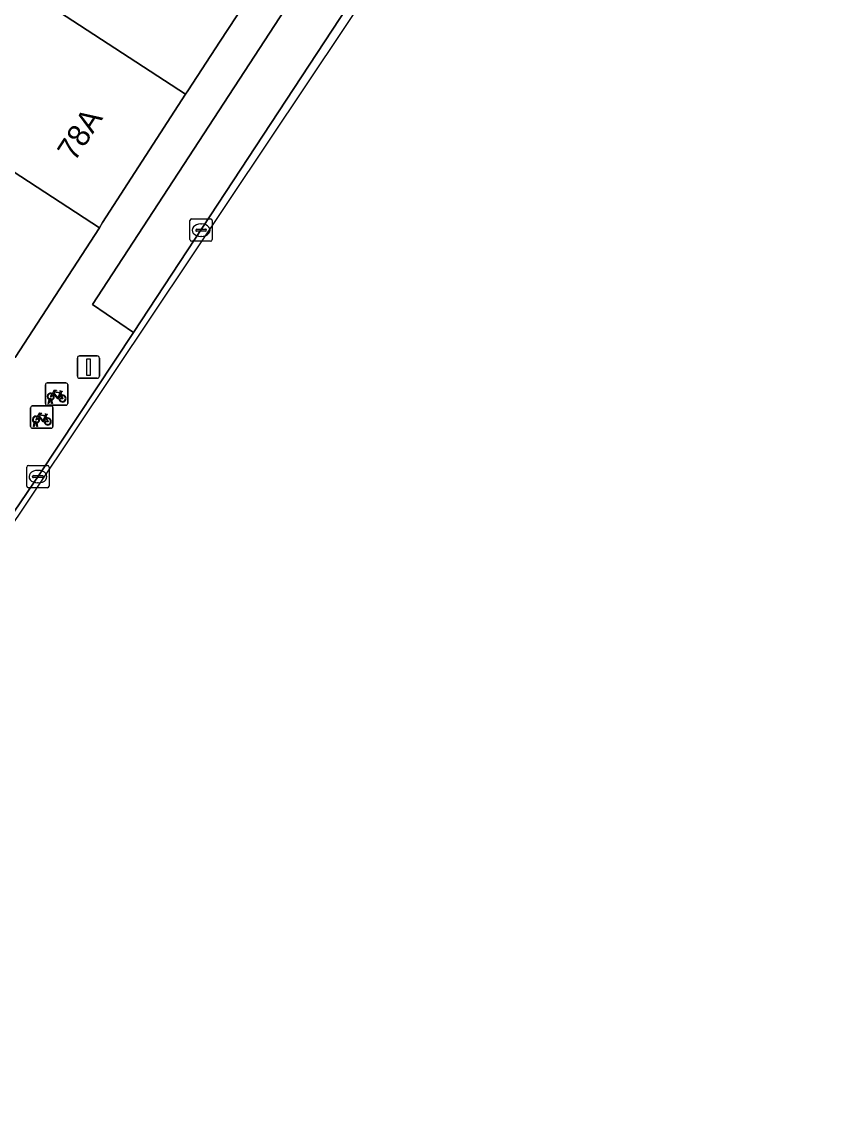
# Model space of a CAD drawing. Extents: x 160102 to 160934, y 382045 to 382923.
# Drawn here: x 160814.44 to 160850.23, y 382615.4 to 382664.84 of the extents above; entities that cross this region are included whole.
import ezdxf

# ---------------------------------------------------------------- set-up
doc = ezdxf.new("R2010")
doc.units = 0
for name, color, linetype in [('IMGEO_Fietsenrek', 7, 'Continuous'), ('IMGEO_Kolk', 7, 'Continuous'), ('IMGEO_Lichtmast', 7, 'Continuous'), ('IMGEO_Pand', 7, 'Continuous'), ('IMGEO_Pand_nummerreeks', 7, 'Continuous'), ('IMGEO_Parkeervlak_open', 7, 'Continuous'), ('IMGEO_Rijbaan_lokaal_gesloten', 7, 'Continuous'), ('IMGEO_Voetpad_open', 7, 'Continuous')]:
    doc.layers.add(name, color=color, linetype=linetype)

msp = doc.modelspace()

# ---------------------------------------------------------------- linework, layer by layer
at = {"layer": 'IMGEO_Fietsenrek'}
for p, q in [((160815.489, 382647.735), (160815.489, 382648.576)), ((160815.489, 382648.576), (160815.489, 382647.735)), ((160815.564, 382648.66), (160816.405, 382648.66)), ((160816.405, 382648.66), (160815.564, 382648.66)), ((160816.489, 382648.585), (160816.489, 382647.744)), ((160816.489, 382647.744), (160816.489, 382648.585)), ((160816.176, 382648.209), (160816.212, 382648.114)), ((160814.901, 382647.629), (160815.742, 382647.629)), ((160815.742, 382647.629), (160814.901, 382647.629)), ((160816.414, 382647.66), (160815.573, 382647.66)), ((160815.573, 382647.66), (160816.414, 382647.66)), ((160815.616, 382647.744), (160815.655, 382647.904)), ((160815.65, 382647.744), (160815.616, 382647.744)), ((160815.685, 382647.892), (160815.65, 382647.744)), ((160815.727, 382647.916), (160815.726, 382647.92)), ((160815.768, 382647.744), (160815.734, 382647.886)), ((160815.758, 382647.927), (160815.759, 382647.92)), ((160815.766, 382647.89), (160815.801, 382647.744)), ((160815.801, 382647.744), (160815.768, 382647.744)), ((160814.826, 382646.704), (160814.826, 382647.545)), ((160814.826, 382647.545), (160814.826, 382646.704)), ((160815.513, 382647.178), (160815.549, 382647.083)), ((160815.826, 382647.554), (160815.826, 382646.713)), ((160815.826, 382646.713), (160815.826, 382647.554)), ((160815.751, 382646.629), (160814.91, 382646.629)), ((160814.91, 382646.629), (160815.751, 382646.629)), ((160814.953, 382646.713), (160814.992, 382646.873)), ((160814.987, 382646.713), (160814.953, 382646.713)), ((160815.022, 382646.861), (160814.987, 382646.713)), ((160815.064, 382646.885), (160815.063, 382646.889)), ((160815.105, 382646.713), (160815.071, 382646.855)), ((160815.095, 382646.896), (160815.096, 382646.889)), ((160815.103, 382646.859), (160815.138, 382646.713)), ((160815.138, 382646.713), (160815.105, 382646.713))]:
    msp.add_line(p, q, dxfattribs=at)
for points in [[(160815.823, 382648.134), (160815.771, 382648.044), (160815.731, 382648.019), (160815.732, 382648.066), (160815.787, 382648.16)], [(160815.802, 382648.186), (160815.897, 382648.35), (160815.983, 382648.336), (160815.985, 382648.327), (160815.929, 382648.316), (160815.902, 382648.271), (160816.158, 382648.23)], [(160816.098, 382647.942), (160816.048, 382647.942), (160815.857, 382648.193), (160815.838, 382648.161)], [(160816.145, 382648.205), (160815.888, 382648.246), (160815.871, 382648.217), (160816.038, 382647.997), (160816.145, 382648.205)], [(160816.193, 382648.107), (160816.163, 382648.184), (160816.054, 382647.966), (160816.097, 382647.966)], [(160816.127, 382647.966), (160816.247, 382647.965), (160816.203, 382648.079)], [(160816.223, 382648.086), (160816.278, 382647.941), (160816.128, 382647.941)], [(160816.158, 382648.23), (160816.183, 382648.279), (160816.177, 382648.283), (160816.154, 382648.287), (160816.142, 382648.294), (160816.141, 382648.297), (160816.143, 382648.302), (160816.238, 382648.287), (160816.24, 382648.277), (160816.23, 382648.264), (160816.218, 382648.258), (160816.204, 382648.264), (160816.176, 382648.209)], [(160815.16, 382647.103), (160815.108, 382647.013), (160815.068, 382646.988), (160815.069, 382647.035), (160815.124, 382647.129)], [(160815.139, 382647.155), (160815.234, 382647.319), (160815.32, 382647.305), (160815.322, 382647.296), (160815.266, 382647.285), (160815.239, 382647.24), (160815.495, 382647.199)], [(160815.435, 382646.911), (160815.385, 382646.911), (160815.194, 382647.162), (160815.175, 382647.13)], [(160815.482, 382647.174), (160815.225, 382647.215), (160815.208, 382647.186), (160815.375, 382646.966), (160815.482, 382647.174)], [(160815.53, 382647.076), (160815.5, 382647.153), (160815.391, 382646.935), (160815.434, 382646.935)], [(160815.495, 382647.199), (160815.52, 382647.248), (160815.514, 382647.252), (160815.491, 382647.256), (160815.479, 382647.263), (160815.478, 382647.266), (160815.48, 382647.271), (160815.575, 382647.256), (160815.577, 382647.246), (160815.567, 382647.233), (160815.555, 382647.227), (160815.541, 382647.233), (160815.513, 382647.178)], [(160815.464, 382646.935), (160815.584, 382646.934), (160815.54, 382647.048)], [(160815.56, 382647.055), (160815.615, 382646.91), (160815.465, 382646.91)]]:
    msp.add_lwpolyline(points, dxfattribs=at)
for centre, radius, start, end in [((160815.567, 382648.582), 0.0779, 92.4484, 184.2845), ((160815.567, 382648.582), 0.0779, 92.4484, 184.2845), ((160816.411, 382648.582), 0.0779, 2.4484, 94.2845), ((160816.411, 382648.582), 0.0779, 2.4484, 94.2845), ((160815.729, 382648.045), 0.159, 62.6766, 242.1369), ((160815.729, 382648.045), 0.129, 63.3192, 238.903), ((160815.729, 382648.045), 0.129, 283.6043, 43.4302), ((160815.729, 382648.045), 0.159, 283.5766, 46.6042), ((160816.256, 382647.961), 0.159, 113.3408, 178.3217), ((160816.256, 382647.961), 0.159, 187.0065, 105.7708), ((160816.256, 382647.961), 0.129, 113.923, 177.9556), ((160816.256, 382647.961), 0.129, 188.6715, 104.5883), ((160814.904, 382647.551), 0.0779, 92.4484, 184.2845), ((160814.904, 382647.551), 0.0779, 92.4484, 184.2845), ((160815.567, 382647.738), 0.0779, 182.4484, 274.2845), ((160815.567, 382647.738), 0.0779, 182.4484, 274.2845), ((160815.709, 382647.916), 0.0499, 12.8025, 158.6934), ((160815.729, 382648.045), 0.159, 253.9967, 271.7867), ((160815.709, 382647.916), 0.0174, 12.8025, 163.4502), ((160815.729, 382648.045), 0.129, 253.415, 269.0204), ((160815.748, 382647.551), 0.0779, 2.4484, 94.2845), ((160815.748, 382647.551), 0.0779, 2.4484, 94.2845), ((160816.411, 382647.738), 0.0779, 272.4484, 4.2845), ((160816.411, 382647.738), 0.0779, 272.4484, 4.2845), ((160815.066, 382647.014), 0.159, 62.6766, 242.1369), ((160815.066, 382647.014), 0.129, 63.3192, 238.903), ((160815.066, 382647.014), 0.129, 283.6043, 43.4302), ((160815.066, 382647.014), 0.159, 283.5766, 46.6042), ((160815.593, 382646.93), 0.159, 113.3408, 178.3217), ((160815.593, 382646.93), 0.159, 187.0065, 105.7708), ((160814.904, 382646.707), 0.0779, 182.4484, 274.2845), ((160814.904, 382646.707), 0.0779, 182.4484, 274.2845), ((160815.046, 382646.885), 0.0499, 12.8025, 158.6934), ((160815.066, 382647.014), 0.159, 253.9967, 271.7867), ((160815.046, 382646.885), 0.0174, 12.8025, 163.4502), ((160815.066, 382647.014), 0.129, 253.415, 269.0204), ((160815.593, 382646.93), 0.129, 113.923, 177.9556), ((160815.593, 382646.93), 0.129, 188.6715, 104.5883), ((160815.748, 382646.707), 0.0779, 272.4484, 4.2845), ((160815.748, 382646.707), 0.0779, 272.4484, 4.2845)]:
    msp.add_arc(centre, radius, start, end, dxfattribs=at)
at = {"layer": 'IMGEO_Kolk'}
for p, q in [((160822.047, 382656.009), (160822.899, 382656.009)), ((160821.972, 382655.083), (160821.972, 382655.935)), ((160822.231, 382655.503), (160822.231, 382655.515)), ((160822.274, 382655.552), (160822.672, 382655.552)), ((160822.46, 382655.789), (160822.485, 382655.789)), ((160822.715, 382655.515), (160822.715, 382655.503)), ((160822.973, 382655.935), (160822.973, 382655.083)), ((160822.899, 382655.009), (160822.047, 382655.009)), ((160822.669, 382655.466), (160822.271, 382655.466)), ((160822.483, 382655.229), (160822.458, 382655.229)), ((160814.655, 382644.034), (160814.655, 382644.886)), ((160814.73, 382644.96), (160815.582, 382644.96)), ((160815.143, 382644.74), (160815.168, 382644.74)), ((160815.656, 382644.886), (160815.656, 382644.034)), ((160814.914, 382644.454), (160814.914, 382644.466)), ((160815.352, 382644.417), (160814.954, 382644.417)), ((160814.957, 382644.503), (160815.355, 382644.503)), ((160815.166, 382644.18), (160815.141, 382644.18)), ((160815.398, 382644.466), (160815.398, 382644.454)), ((160815.582, 382643.96), (160814.73, 382643.96))]:
    msp.add_line(p, q, dxfattribs=at)
for points in [[(160822.047, 382656.009), (160822.899, 382656.009)], [(160821.972, 382655.083), (160821.972, 382655.935)], [(160822.973, 382655.935), (160822.973, 382655.083)], [(160822.899, 382655.009), (160822.047, 382655.009)], [(160814.655, 382644.034), (160814.655, 382644.886)], [(160814.73, 382644.96), (160815.582, 382644.96)], [(160815.656, 382644.886), (160815.656, 382644.034)], [(160815.582, 382643.96), (160814.73, 382643.96)]]:
    msp.add_lwpolyline(points, dxfattribs=at)
for centre, radius, start, end in [((160822.049, 382655.933), 0.0765, 91.552, 178.448), ((160822.049, 382655.933), 0.0765, 91.552, 178.448), ((160822.897, 382655.933), 0.0765, 1.552, 88.448), ((160822.897, 382655.933), 0.0765, 1.552, 88.448), ((160822.271, 382655.512), 0.0403, 85.8775, 175.7526), ((160822.268, 382655.502), 0.0366, 178.938, 274.7102), ((160822.672, 382655.509), 0.043, 264.8664, 352.4533), ((160822.676, 382655.514), 0.0386, 1.7309, 96.639), ((160822.049, 382655.085), 0.0765, 181.552, 268.448), ((160822.049, 382655.085), 0.0765, 181.552, 268.448), ((160822.897, 382655.085), 0.0765, 271.552, 358.448), ((160822.897, 382655.085), 0.0765, 271.552, 358.448), ((160814.732, 382644.884), 0.0765, 91.552, 178.448), ((160814.732, 382644.884), 0.0765, 91.552, 178.448), ((160815.58, 382644.884), 0.0765, 1.552, 88.448), ((160815.58, 382644.884), 0.0765, 1.552, 88.448), ((160814.954, 382644.463), 0.0403, 85.8775, 175.7526), ((160814.951, 382644.453), 0.0366, 178.938, 274.7102), ((160815.355, 382644.46), 0.043, 264.8664, 352.4533), ((160815.359, 382644.465), 0.0386, 1.7309, 96.639), ((160814.732, 382644.036), 0.0765, 181.552, 268.448), ((160814.732, 382644.036), 0.0765, 181.552, 268.448), ((160815.58, 382644.036), 0.0765, 271.552, 358.448), ((160815.58, 382644.036), 0.0765, 271.552, 358.448)]:
    msp.add_arc(centre, radius, start, end, dxfattribs=at)
for centre, major_axis, ratio, start_param, end_param in [((160822.459, 382655.509), (-0.387, 0.002), 0.722429, 4.712389, 7.853982), ((160822.484, 382655.509), (-0.39, 0.002), 0.717154, 1.570796, 4.712389), ((160815.142, 382644.46), (-0.387, 0.002), 0.722429, 4.712389, 7.853982), ((160815.167, 382644.46), (-0.39, 0.002), 0.717154, 1.570796, 4.712389)]:
    msp.add_ellipse(centre, major_axis=major_axis, ratio=ratio, start_param=start_param, end_param=end_param, dxfattribs=at)
at = {"layer": 'IMGEO_Lichtmast'}
for p, q in [((160816.921, 382648.967), (160816.921, 382649.767)), ((160816.921, 382649.767), (160816.921, 382648.967)), ((160817.021, 382649.867), (160817.811, 382649.867)), ((160817.811, 382649.867), (160817.021, 382649.867)), ((160817.911, 382649.767), (160817.911, 382648.967)), ((160817.911, 382648.967), (160817.911, 382649.767)), ((160817.811, 382648.867), (160817.021, 382648.867)), ((160817.021, 382648.867), (160817.811, 382648.867))]:
    msp.add_line(p, q, dxfattribs=at)
msp.add_lwpolyline([(160817.341, 382649.742), (160817.491, 382649.742), (160817.491, 382648.992), (160817.341, 382648.992), (160817.341, 382649.742)], dxfattribs=at)
for centre, start, end in [((160817.021, 382649.767), 90, 180), ((160817.021, 382649.767), 90, 180), ((160817.811, 382649.767), 0, 90), ((160817.811, 382649.767), 360, 90), ((160817.021, 382648.967), 180, 270), ((160817.021, 382648.967), 180, 270), ((160817.811, 382648.967), 270, 0), ((160817.811, 382648.967), 270, 0)]:
    msp.add_arc(centre, 0.1, start, end, dxfattribs=at)
at = {"layer": 'IMGEO_Pand'}
for points in [[(160811.692, 382669.149), (160815.629, 382665.629), (160815.776, 382665.498), (160821.774, 382661.597), (160821.871, 382661.747), (160823.328, 382663.975), (160825.508, 382667.307), (160819.142, 382671.084), (160819.247, 382671.247), (160818.637, 382671.639), (160818.489, 382671.463), (160815.298, 382674.747)], [(160811.692, 382669.149), (160809.855, 382666.296), (160802.642, 382672.559), (160800.044, 382669.827), (160805.852, 382664.303), (160807.624, 382662.832), (160809.226, 382661.801), (160811.951, 382660.046), (160811.713, 382659.676), (160811.925, 382659.508), (160817.908, 382655.617), (160818.057, 382655.846), (160821.774, 382661.597), (160815.776, 382665.498), (160815.629, 382665.629)], [(160805.646, 382657.17), (160808.797, 382654.861), (160808.143, 382653.695), (160814.13, 382649.8), (160817.908, 382655.617), (160811.925, 382659.508), (160811.713, 382659.676), (160811.951, 382660.046), (160809.226, 382661.801), (160806.357, 382657.355), (160805.963, 382657.609)]]:
    msp.add_lwpolyline(points, close=True, dxfattribs=at)
at = {"layer": 'IMGEO_Parkeervlak_open'}
msp.add_lwpolyline([(160829.732, 382666.583), (160827.814, 382667.842), (160817.594, 382652.178), (160819.446, 382650.913)], close=True, dxfattribs=at)
at = {"layer": 'IMGEO_Rijbaan_lokaal_gesloten'}
msp.add_lwpolyline([(160850.227, 382700.029), (160839.541, 382682.417), (160830.982, 382668.497), (160829.732, 382666.583), (160819.446, 382650.913), (160815.241, 382644.584), (160812.358, 382640.352), (160805.417, 382630.29), (160798.913, 382620.841), (160796.011, 382616.61), (160795.431, 382615.795), (160796.001, 382615.398), (160835.883, 382675.025), (160849.532, 382695.433)], dxfattribs=at)
at = {"layer": 'IMGEO_Voetpad_open'}
for points in [[(160815.241, 382644.584), (160819.446, 382650.913), (160817.594, 382652.178), (160827.814, 382667.842), (160829.732, 382666.583), (160830.982, 382668.497), (160839.541, 382682.417), (160850.227, 382700.029)], [(160825.508, 382667.307), (160823.328, 382663.975), (160821.871, 382661.747), (160821.774, 382661.597), (160818.057, 382655.846), (160817.908, 382655.617), (160814.13, 382649.8)], [(160812.358, 382640.352), (160815.241, 382644.584)]]:
    msp.add_lwpolyline(points, dxfattribs=at)

# ---------------------------------------------------------------- texts
at = {"layer": 'IMGEO_Pand_nummerreeks'}
msp.add_text('78A', height=1, rotation=57.1191, dxfattribs=at).set_placement((160816.801, 382658.546))

doc.saveas('drawing.dxf')
